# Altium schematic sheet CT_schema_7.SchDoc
size 372 x 335 mm
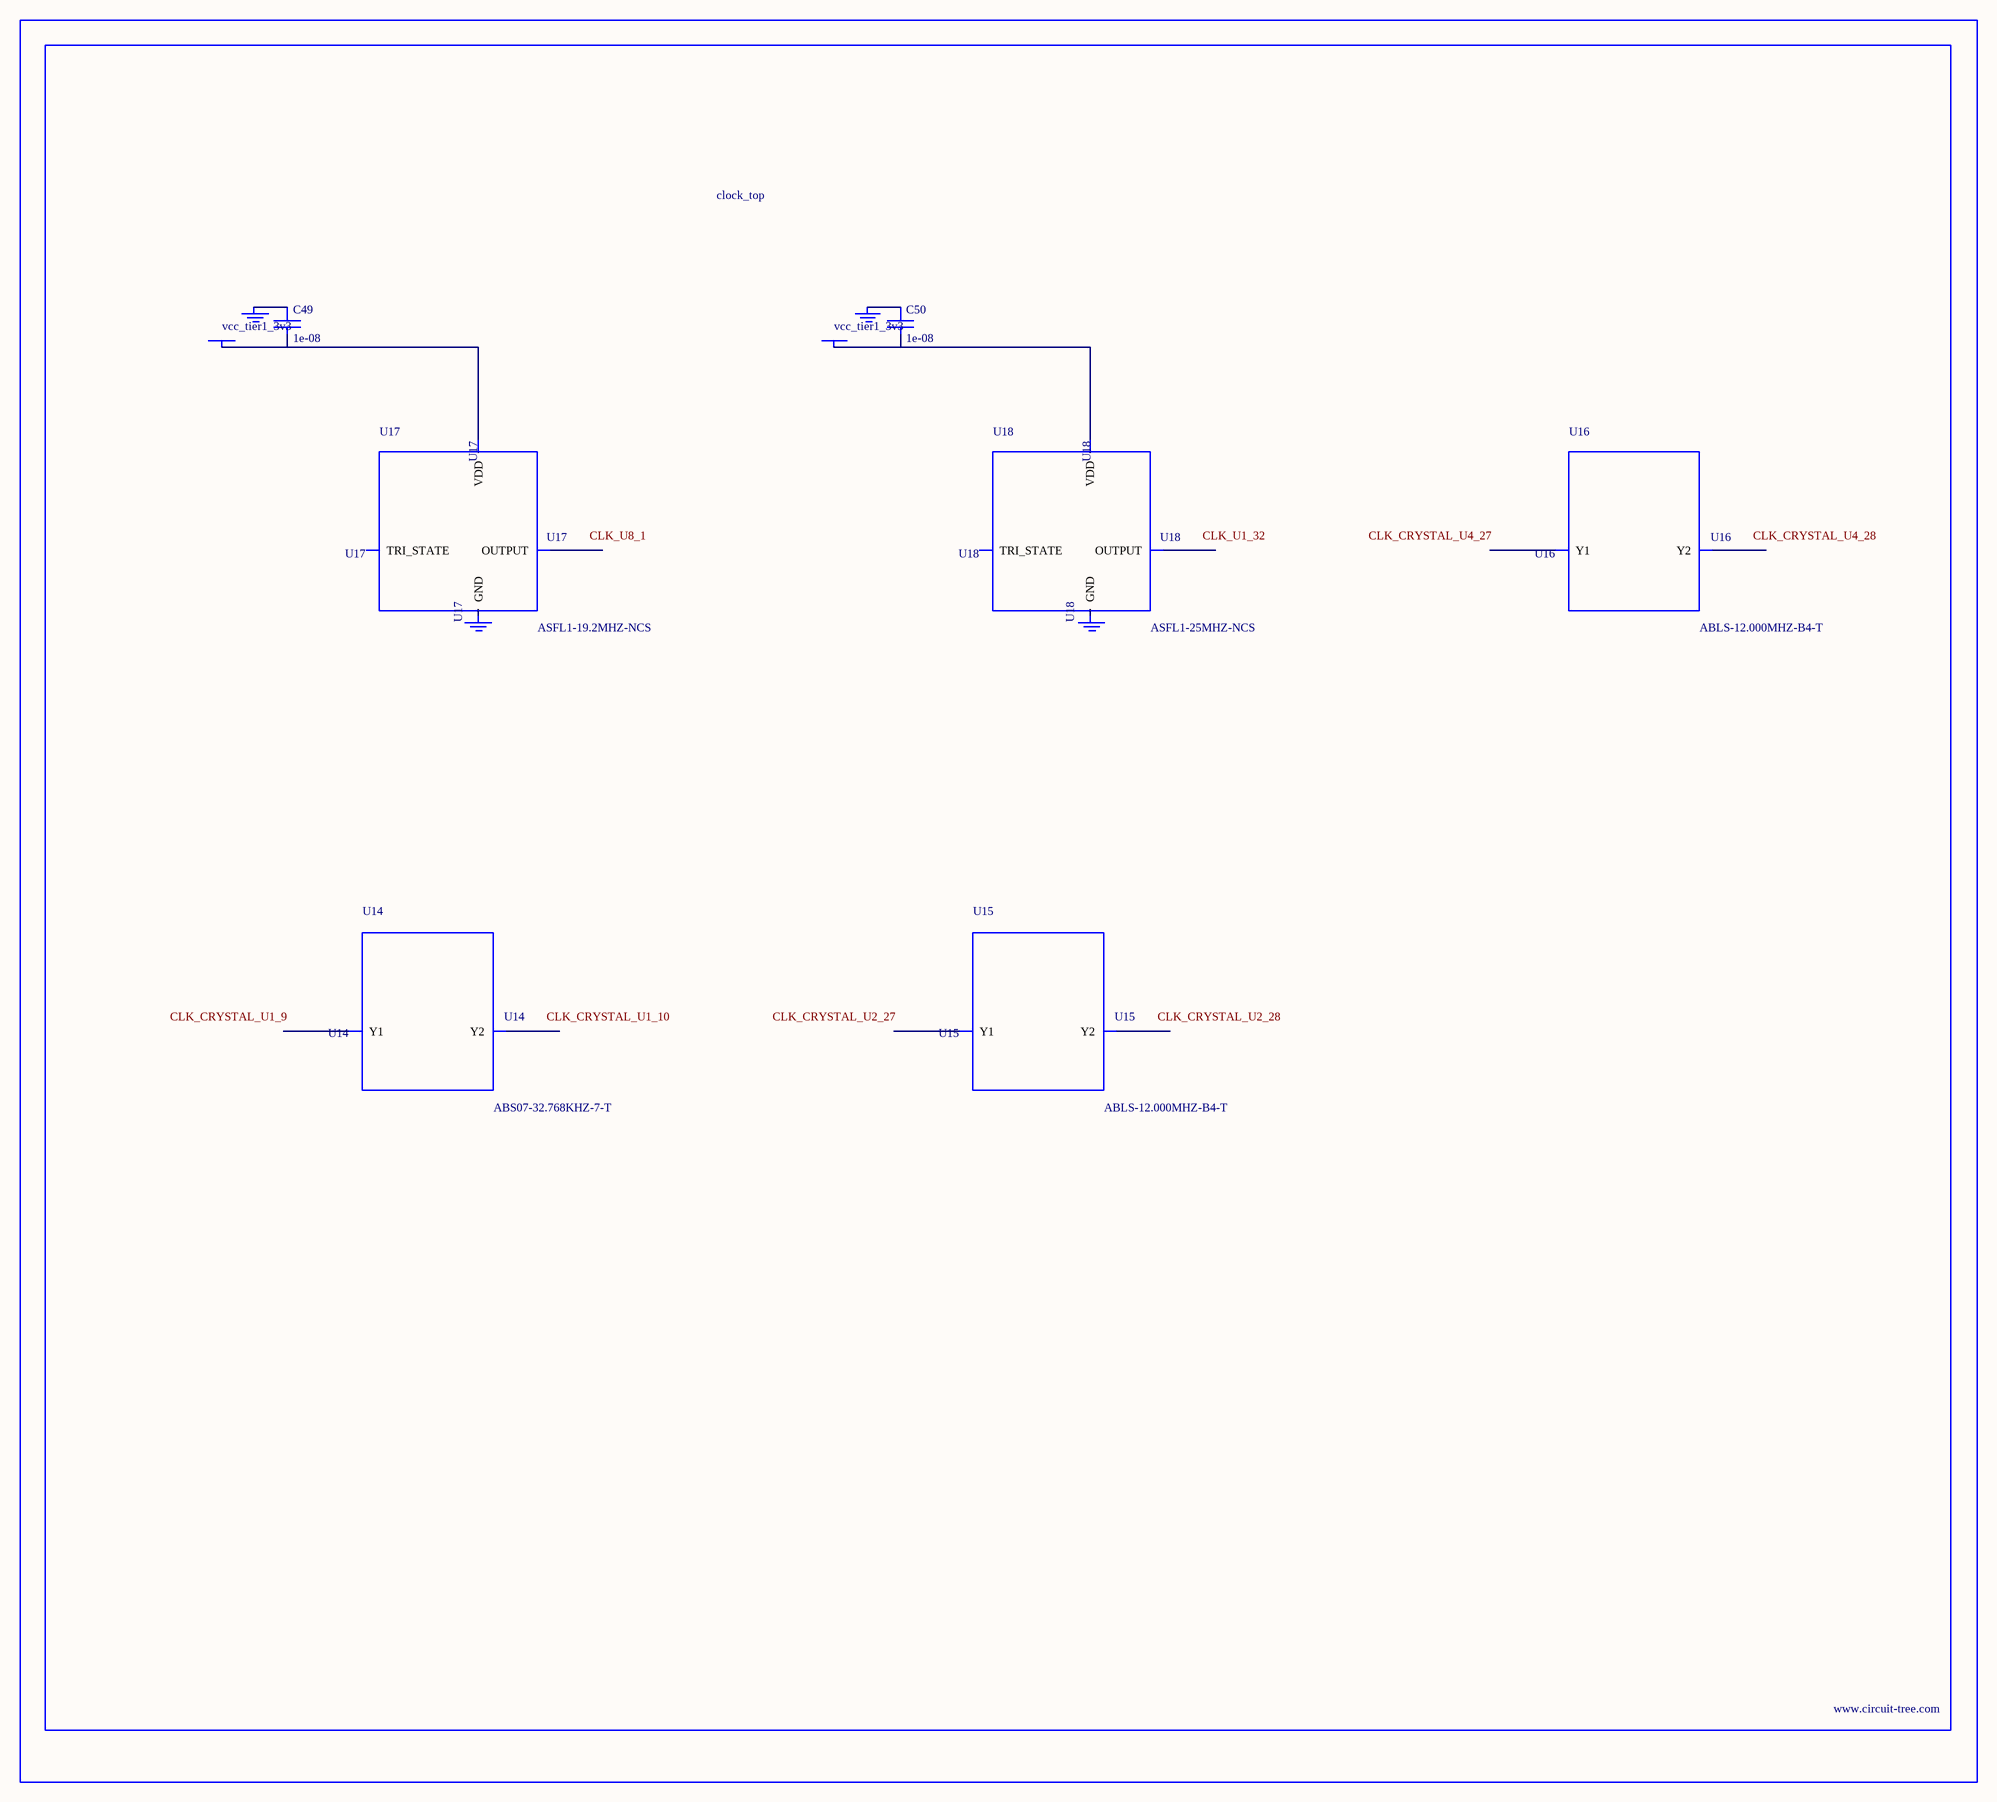
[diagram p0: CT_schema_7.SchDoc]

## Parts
BORDER6  (no value)
C49  1e-08  [C0402]
C50  1e-08  [C0402]
GND_INSTANCE_6_0  (no value)
GND_INSTANCE_6_1  (no value)
GND_INSTANCE_6_2  (no value)
GND_INSTANCE_6_3  (no value)
POWER_INSTANCE_6_0  vcc_tier1_3v3
POWER_INSTANCE_6_1  vcc_tier1_3v3
U14  ABS07-32.768KHZ-7-T  [ABS07-32.768KHZ-7-T]
U15  ABLS-12.000MHZ-B4-T  [ABLS-12.000MHZ-B4-T]
U16  ABLS-12.000MHZ-B4-T  [ABLS-12.000MHZ-B4-T]
U17  ASFL1-19.2MHZ-NCS  [ASFL1]
U18  ASFL1-25MHZ-NCS  [ASFL1]

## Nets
NetC49_1: C49.1 GND_INSTANCE_6_0.0(GND)
NetC49_2: C49.2 POWER_INSTANCE_6_0.0(PWR) U17.4(VDD)
NetC50_1: C50.1 GND_INSTANCE_6_2.0(GND)
NetC50_2: C50.2 POWER_INSTANCE_6_1.0(PWR) U18.4(VDD)

Not connected (* = marked no-connect by the designer): GND_INSTANCE_6_1 0(GND); GND_INSTANCE_6_3 0(GND); U14 1(Y1) 2(Y2); U15 1(Y1) 2(Y2); U16 1(Y1) 2(Y2); U17 1(TRI_STATE) 2(GND) 3(OUTPUT); U18 1(TRI_STATE) 2(GND) 3(OUTPUT)

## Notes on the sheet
- Labels drawn without touching a wire or pin: CLK_CRYSTAL_U1_9, CLK_CRYSTAL_U1_10, CLK_CRYSTAL_U2_27, CLK_CRYSTAL_U2_28, CLK_CRYSTAL_U4_27, CLK_CRYSTAL_U4_28, CLK_U1_32, CLK_U8_1

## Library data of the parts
BORDER6 = BORDER_PAGE6
C49 C50 = C0402C103K3RAC
GND_INSTANCE_6_0-GND_INSTANCE_6_3 = GND
POWER_INSTANCE_6_0 POWER_INSTANCE_6_1 = PWR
